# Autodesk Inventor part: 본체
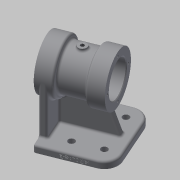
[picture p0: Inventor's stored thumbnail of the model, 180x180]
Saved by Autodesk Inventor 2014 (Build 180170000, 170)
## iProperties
Created: 2020-06
Part Number: 본체
Material: Generic
Document SubType Name: Modeling
Designer: kh
Density: 1 g/cm^3
Appearance: Default
Author: kh
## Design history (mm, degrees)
sketch "Sketch1"
  geometry: L1 (-49, 45)-(49, 45); L2 (49, 45)-(49, -45); L3 (49, -45)-(-49, -45); L4 (-49, -45)-(-49, 45); L5 (-49, 45)-(49, -45); L6 (49, 45)-(-49, -45); 1 further point
  constraints: 12 end point, 2 midpoint, 2 parallel, 1 horizontal, 1 perpendicular
  dimensions: "d0" = 98 distance of L2.end L3.end; "d1" = 90 distance of L1.end L2.end
extrude "Extrusion1" new body sketch "Sketch1" distance "d2" = 10; taper "d3" = 0 deg
workplane "Work Plane2"
sketch "Sketch2"
  geometry: L1 (-29, 80)-(141, 80); L2 (0, 0)-(90, 0) reference; L3 (-5, 115)-(-5, 80); L4 (0, 0)-(0, 10) reference; L5 (-5, 115)-(17, 115); L6 (73, 115)-(73, 80); L7 (73, 115)-(51, 115); L8 (17, 109)-(51, 109); L9 (17, 115)-(17, 109); L10 (51, 115)-(51, 109); L11 (34, 109)-(34, 80); 1 further point
  constraints: 18 end point, 7 perpendicular, 3 point on line, 1 horizontal, 1 midpoint, 1 parallel
  dimensions: "d5" = 80 distance between parallel lines of L2 L1; "d6" = 5 distance between parallel lines of L4 L3; "d7" = 22 distance of L3.start L5.end; "d8" = 70 diameter of L5 L1; "d9" = 78 distance between parallel lines of L6 L3; "d10" = 22 distance of L6.start L7.end; "d11" = 70 diameter of L7 L1 (= d8); "d12" = 58 diameter of L8 L1
revolve "Revolution1" sketch "Sketch2" stored, may be unused: angle "d13" = 90 deg
sketch "Sketch4"
  geometry: L1 (0, 0)-(90, 0) reference; L2 (0, 0)-(0, 10) reference; L3 (90, 10)-(0, 10) reference; L4 (90, 0)-(90, 10) reference; L5 (51, 45)-(73, 45) reference; L6 (-5, 45)-(17, 45) reference; L7 (0, 10)-(0, 63); L8 (78, 10)-(61.493, 55.354); L9 (61.493, 55.354)-(0, 63); L10 (78, 10)-(0, 10); 1 further point
  constraints: 8 end point, 2 perpendicular, 1 point on line
  dimensions: "d17" = 70 deg angle of L3 L8; "d18" = 12 distance from line of L4 L8.start
extrude "Extrusion2" join sketch "Sketch4" stored distance "d19" = 10; taper "d20" = 0 deg
sketch "Sketch5"
  geometry: L1 (0, 0)-(0, 10) reference; L2 (14, 80)-(14, 5); L3 (84, 80)-(84, 5); L4 (84, 5)-(14, 5); L5 (14, 80)-(84, 80); A1 r 35 centre (49, 80) between (14, 80) and (84, 80) reference; 1 further point
  constraints: 8 end point, 2 parallel, 2 perpendicular, 2 point on circle, 2 tangent
extrude "Extrusion3" join sketch "Sketch5" distance "d21" = 10; taper "d22" = 0 deg
workplane "Work Plane4"
  workplane "Work Plane3"
sketch "Sketch7"
  geometry: L1 (-35, 39)-(35, 39) reference; L2 (-35, -39)-(35, -39) reference; L3 (0, 39)-(0, -39); C1 r 6 at (0, 0); 1 further point
  constraints: 3 midpoint, 2 end point, 1 centre point
  dimensions: "d27" = 12 diameter of C1
extrude "Extrusion5" join sketch "Sketch7" distance "d28" = 5; taper "d29" = 0 deg
sketch "Sketch8"
  geometry: L1 (45, 50)-(115, 50) reference; L2 (45, -28)-(115, -28) reference; L3 (80, -28)-(80, 50); L4 (103.5, 50)-(103.5, 32); L5 (103.5, 32)-(100, 32); L6 (100, 32)-(100, 26); L7 (104, 26)-(104, -4); L8 (100, 26)-(104, 26); L9 (104, -4)-(100, -4); L10 (100, -4)-(100, -10); L11 (100, -10)-(103.5, -10); L12 (103.5, -10)-(103.5, -28); L13 (103.5, -28)-(80, -28); L14 (103.5, 50)-(80, 50); 1 further point
  constraints: 24 end point, 5 parallel, 4 perpendicular, 2 collinear, 2 midpoint, 2 point on line
  dimensions: "d31" = 47 diameter of L4 L3; "d32" = 18 distance of L4.start L4.end; "d33" = 6 distance of L5.end L6.end; "d34" = 48 diameter of L7 L3; "d35" = 47 diameter of L12 L3 (= d31); "d36" = 6 distance between parallel lines of L9 L11; "d37" = 40 diameter of L10 L3; "d38" = 40 diameter of L6 L3 (= d37); "d39" = 18 distance between parallel lines of L2 L11 (= d32)
revolve "Revolution2" sketch "Sketch8" stored, may be unused: angle "d40" = 90 deg
sketch "Sketch9"
  geometry: C1 r 35 at (0, 0) reference; A1 r 28.5 centre (0, 0) between (0, 28.5) and (28.5, 0); 3 further points
  constraints: 4 point on circle, 1 centre point, 1 coincident
  dimensions: "d41" = 57 diameter of A1
hole "Hole1" sketch "Sketch9" at (0, 28.5), (28.5, 0), (-28.5, 0), (0, -28.5) diameter "d42" = 3.242; stored, may be unused: countersink angle "d46" = 90 deg, drill point angle "d48" = 118 deg; dims "d43" = 10, "d44" = 4, "d45" = 2, "d47" = 12
workplane "Work Plane5"
mirror "Mirror1"
sketch "Sketch10"
  geometry: L1 (49, -45)-(-49, -45) reference; L2 (0, -45)-(0, 45); L3 (-49, 45)-(49, 45) reference; 5 further points
  constraints: 2 end point, 2 midpoint, 2 symmetric about line, 1 perpendicular, 1 vertical alignment
  dimensions: "d49" = 36 distance of point (-29, 25) point (-29, -11); "d50" = 70 distance from line of L1 point (-29, 25); "d51" = 29 distance from line of L2 point (-29, 25)
hole "Hole2" sketch "Sketch10" at (-29, -11), (-29, 25), (29, 25), (29, -11) diameter "d52" = 9; stored, may be unused: countersink angle "d56" = 90 deg, drill point angle "d58" = 118 deg; dims "d53" = 10, "d54" = 4, "d55" = 2, "d57" = 12
hole "Hole3" diameter "d61" = 5.188; stored, may be unused: countersink angle "d65" = 90 deg, drill point angle "d67" = 118 deg; dims "d59" = 10, "d60" = 10, "d62" = 20, "d63" = 4, "d64" = 2, "d66" = 25
fillet "Fillet1" dims "d68" = 3
fillet "Fillet2" dims "d69" = 3
fillet "Fillet3" dims "d70" = 3
fillet "Fillet4" dims "d71" = 3
fillet "Fillet5" dims "d72" = 3, "d73" = 0.3
chamfer "Chamfer1" distance "d74" = 1; stored, may be unused: second distance "d75" = 2, angle "d76" = 45 deg
fillet "Fillet6" dims "d77" = 20
fillet "Fillet7" dims "d78" = 3
sketch "Sketch11"
  geometry: L1 (67, 0)-(0, 0) reference; L2 (-3, 7)-(-3, 0) reference; 2 further points
  constraints: 1 other
  dimensions: "d79" = 45 distance from line of L2 point (42, 4); "d80" = 4 distance from line of L1 point (42, 4)
emboss "Emboss1" sketch "Sketch11" dims "d0" = 98, "d1" = 90, "d11" = 70 (= d8), "d81" = 0.5, "d82" = 0
body "Solid1"
node "Projected Loop1"
node "Projected Loop2"
other parameters: "d26" = 3
